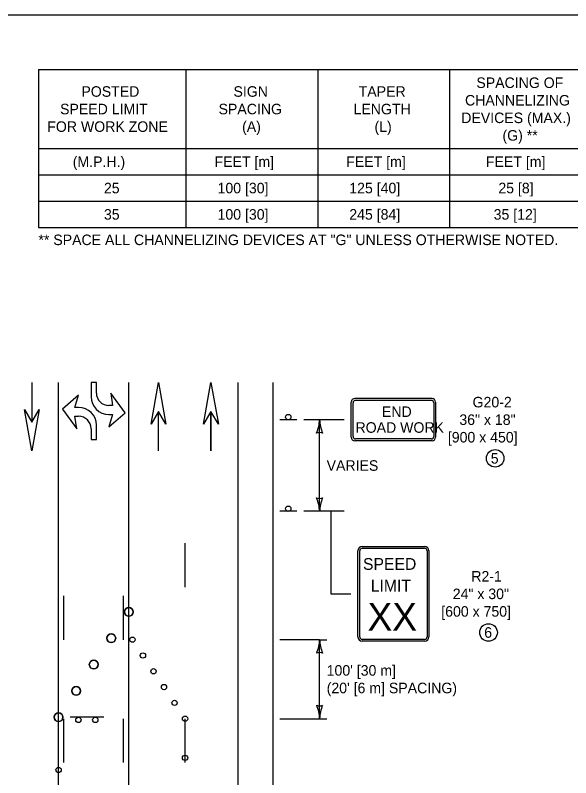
# Model space of a CAD drawing. Extents: x 49991.4 to 50021, y 49987.6 to 50011.4.
# Drawn here: x 50002.533 to 50005.696, y 50006.919 to 50011.263 of the extents above; entities that cross this region are included whole.
import ezdxf

# ---------------------------------------------------------------- set-up
doc = ezdxf.new("R2010")
doc.units = 0
for name, color, linetype in [('Level 1', 7, 'Continuous'), ('Level 2', 7, 'Continuous'), ('Level 3', 7, 'Continuous')]:
    doc.layers.add(name, color=color, linetype=linetype)

msp = doc.modelspace()

# ---------------------------------------------------------------- linework, layer by layer
at = {"layer": 'Level 1'}
for p, q in [((50002.6282, 50009.1708), (50002.6282, 50008.9449)), ((50002.6284, 50009.1708), (50002.6284, 50008.9449)), ((50002.7802, 50000.6526), (50002.7802, 50009.1708)), ((50002.9955, 50009.1708), (50002.9649, 50009.1708)), ((50002.9649, 50009.1708), (50002.9649, 50009.09)), ((50002.9955, 50009.1102), (50002.9955, 50009.1708)), ((50003.1802, 50000.6526), (50003.1802, 50009.1708)), ((50003.8002, 50009.1708), (50003.8002, 50000.6526)), ((50004.0002, 50009.1708), (50004.0002, 50000.6526)), ((50002.8934, 50009.0995), (50002.8015, 50009.0187)), ((50002.873, 50009.0288), (50002.8934, 50009.0995)), ((50003.1588, 50008.999), (50003.0772, 50009.1102)), ((50003.0772, 50009.1102), (50003.0874, 50009.0394)), ((50003.0609, 50009.0445), (50003.0609, 50009.0445)), ((50003.0874, 50009.0394), (50003.067, 50009.0394)), ((50004.4465, 50008.8591), (50004.4465, 50009.0591)), ((50004.4565, 50008.8641), (50004.4565, 50009.0541)), ((50004.9065, 50009.0791), (50004.4665, 50009.0791)), ((50004.9015, 50009.0691), (50004.4715, 50009.0691)), ((50004.9165, 50009.0541), (50004.9165, 50008.8641)), ((50004.9265, 50009.0591), (50004.9265, 50008.8591)), ((50002.8015, 50009.0187), (50002.8832, 50008.9075)), ((50002.8934, 50009.0288), (50002.873, 50009.0288)), ((50003.067, 50008.9181), (50003.1588, 50008.999)), ((50003.3491, 50008.7807), (50003.3491, 50009.0066)), ((50003.3495, 50008.7807), (50003.3495, 50009.0066)), ((50003.6477, 50008.7807), (50003.6477, 50009.0066)), ((50003.6481, 50008.7807), (50003.6481, 50009.0066)), ((50002.8832, 50008.9075), (50002.873, 50008.9783)), ((50002.873, 50008.9783), (50002.8934, 50008.9783)), ((50002.8995, 50008.9732), (50002.8995, 50008.9732)), ((50003.067, 50008.9889), (50003.0874, 50008.9889)), ((50003.0874, 50008.9889), (50003.067, 50008.9181)), ((50004.1362, 50008.9591), (50004.0402, 50008.9591)), ((50002.9649, 50008.9075), (50002.9649, 50008.8468)), ((50002.9955, 50008.8468), (50002.9955, 50008.9277)), ((50002.9649, 50008.8468), (50002.9955, 50008.8468)), ((50004.9064, 50008.8391), (50004.4664, 50008.8391)), ((50004.9015, 50008.8491), (50004.4715, 50008.8491)), ((50004.1362, 50008.437), (50004.0402, 50008.437)), ((50003.5003, 50008.0059), (50003.5003, 50008.2559)), ((50004.4839, 50007.7222), (50004.4839, 50008.2116)), ((50004.4944, 50007.7222), (50004.4944, 50008.2116)), ((50004.5092, 50008.237), (50004.8636, 50008.237)), ((50004.5092, 50008.2264), (50004.8636, 50008.2264)), ((50004.6864, 50008.237), (50004.6864, 50008.237)), ((50004.8784, 50008.2116), (50004.8784, 50007.7222)), ((50004.8889, 50008.2116), (50004.8889, 50007.7222)), ((50002.8102, 50007.7059), (50002.8102, 50007.9559)), ((50003.1502, 50007.7059), (50003.1502, 50007.9559)), ((50004.8636, 50007.7074), (50004.5092, 50007.7074)), ((50004.8636, 50007.6969), (50004.5092, 50007.6969)), ((50002.8102, 50007.0059), (50002.8102, 50007.2559)), ((50002.9412, 50007.2639), (50002.8452, 50007.2639)), ((50003.0372, 50007.2639), (50002.9412, 50007.2639)), ((50003.1502, 50007.0059), (50003.1502, 50007.2559)), ((50003.5003, 50007.0059), (50003.5003, 50007.2559))]:
    msp.add_line(p, q, dxfattribs=at)
for points in [[(50008.6146, 50011.2628), (50000.3356, 50011.2628), (50000.3356, 50000.0624), (50008.6146, 50000.0624)], [(50003.3075, 50008.9343), (50003.3491, 50009.1708), (50003.3911, 50008.9343), (50003.3491, 50009.0065)], [(50003.6061, 50008.9343), (50003.6477, 50009.1708), (50003.6897, 50008.9343), (50003.6477, 50009.0065)], [(50002.6702, 50009.0172), (50002.6284, 50008.7807), (50002.5866, 50009.0172), (50002.6284, 50008.945)]]:
    msp.add_lwpolyline(points, close=True, dxfattribs=at)
for centre, radius in [((50004.0881, 50008.9743), 0.0152), ((50004.0881, 50008.4521), 0.0152), ((50003.1802, 50007.8639), 0.025), ((50003.0802, 50007.7139), 0.025), ((50003.2005, 50007.7059), 0.015), ((50003.2604, 50007.6159), 0.015), ((50002.9802, 50007.5639), 0.025), ((50003.3204, 50007.5259), 0.015), ((50002.8802, 50007.4139), 0.025), ((50003.3804, 50007.4359), 0.015), ((50003.4404, 50007.3459), 0.015), ((50002.7802, 50007.2639), 0.025), ((50002.8932, 50007.2487), 0.0152), ((50002.9892, 50007.2487), 0.0152), ((50003.5003, 50007.2559), 0.015), ((50003.5003, 50007.0329), 0.015), ((50002.7802, 50006.9639), 0.015)]:
    msp.add_circle(centre, radius, dxfattribs=at)
for centre, radius, start, end in [((50004.4665, 50009.0591), 0.02, 90, 180), ((50004.4715, 50009.0541), 0.015, 90, 180), ((50004.9015, 50009.0541), 0.015, 360, 90), ((50004.9065, 50009.0591), 0.02, 360, 90), ((50004.4715, 50008.8641), 0.015, 180, 270), ((50004.9015, 50008.8641), 0.015, 270, 360), ((50004.4664, 50008.8591), 0.02, 180, 270), ((50004.9064, 50008.8591), 0.02, 270, 360), ((50004.5092, 50008.2116), 0.0253, 90, 180), ((50004.5092, 50008.2116), 0.0148, 90, 180), ((50004.8636, 50008.2116), 0.0253, 0, 90), ((50004.8636, 50008.2116), 0.0148, 0, 90), ((50003.1802, 50007.8639), 0.025, 0, 180), ((50003.1802, 50007.8639), 0.025, 180, 0), ((50003.0802, 50007.7139), 0.025, 0, 180), ((50003.0802, 50007.7139), 0.025, 180, 0), ((50004.5092, 50007.7222), 0.0253, 180, 270), ((50004.5092, 50007.7222), 0.0148, 180, 270), ((50004.8636, 50007.7222), 0.0148, 270, 360), ((50004.8636, 50007.7222), 0.0253, 270, 360), ((50002.9802, 50007.5639), 0.025, 0, 180), ((50002.9802, 50007.5639), 0.025, 180, 0), ((50002.8802, 50007.4139), 0.025, 0, 180), ((50002.8802, 50007.4139), 0.025, 180, 0), ((50002.7802, 50007.2639), 0.025, 0, 180), ((50002.7802, 50007.2639), 0.025, 180, 0)]:
    msp.add_arc(centre, radius, start, end, dxfattribs=at)
for centre, major_axis in [((50003.067, 50009.09), (-0.1021, 0)), ((50003.067, 50009.1102), (-0.0715, 0)), ((50002.8934, 50008.9277), (0.1021, 0)), ((50002.8934, 50008.9075), (0.0715, 0))]:
    msp.add_ellipse(centre, major_axis=major_axis, ratio=0.990099, start_param=0, end_param=1.570796, dxfattribs=at)
at = {"layer": 'Level 2'}
for p, q in [((50002.6653, 50010.9535), (50006.5953, 50010.9535)), ((50002.6653, 50010.9535), (50002.6653, 50010.0535)), ((50003.5053, 50010.9535), (50003.5053, 50010.0535)), ((50004.2553, 50010.9535), (50004.2553, 50010.0535)), ((50005.0053, 50010.9535), (50005.0053, 50010.0535)), ((50002.6653, 50010.5035), (50006.5953, 50010.5035)), ((50002.6653, 50010.3535), (50006.5953, 50010.3535)), ((50002.6653, 50010.2035), (50006.5953, 50010.2035)), ((50002.6653, 50010.0535), (50006.5953, 50010.0535))]:
    msp.add_line(p, q, dxfattribs=at)
for centre in [(50005.2657, 50008.739), (50005.2281, 50007.7468)]:
    msp.add_circle(centre, 0.0501, dxfattribs=at)
at = {"layer": 'Level 3'}
for p, q in [((50004.4065, 50008.9591), (50004.1762, 50008.9591)), ((50004.2662, 50008.437), (50004.2662, 50008.9591)), ((50004.4065, 50008.437), (50004.1762, 50008.437)), ((50004.2665, 50007.7059), (50004.0402, 50007.7059)), ((50004.2665, 50007.2559), (50004.2665, 50007.7059)), ((50004.2665, 50007.7059), (50004.3065, 50007.7059)), ((50004.2665, 50007.2559), (50004.2665, 50007.5714)), ((50004.0402, 50007.2559), (50004.3065, 50007.2559))]:
    msp.add_line(p, q, dxfattribs=at)
msp.add_lwpolyline([(50004.3306, 50008.437), (50004.3306, 50007.9669), (50004.4439, 50007.9669)], dxfattribs=at)
for centre, radius, start, end in [((50004.0441, 50008.9683), 0.2223, 337.456, 357.6395), ((50004.4989, 50008.9706), 0.233, 182.8273, 202.0772), ((50004.2662, 50008.8309), 0.0548, 72.1388, 107.8612), ((50004.2662, 50008.5652), 0.0548, 252.1388, 287.8612), ((50004.0335, 50008.4255), 0.233, 2.8273, 22.0772), ((50004.4883, 50008.4278), 0.2223, 157.456, 177.6395), ((50004.0444, 50007.7151), 0.2223, 337.456, 357.6395), ((50004.4992, 50007.7174), 0.233, 182.8273, 202.0772), ((50004.2665, 50007.5777), 0.0548, 72.1388, 107.8612), ((50004.2665, 50007.3841), 0.0548, 252.1388, 287.8612), ((50004.0338, 50007.2444), 0.233, 2.8273, 22.0772), ((50004.4886, 50007.2467), 0.2223, 157.456, 177.6395)]:
    msp.add_arc(centre, radius, start, end, dxfattribs=at)

# ---------------------------------------------------------------- texts
at = {"layer": 'Level 1'}
for s, p in [('END', (50004.6213, 50008.9745)), ('ROAD WORK', (50004.4706, 50008.8845))]:
    msp.add_text(s, height=0.06, rotation=360, dxfattribs=at).set_placement(p)
for s, height, p in [('SPEED', 0.06695, (50004.5133, 50008.1037)), ('LIMIT', 0.06695, (50004.5576, 50007.9799)), ('XX', 0.15772, (50004.5393, 50007.758))]:
    msp.add_text(s, height=height, dxfattribs=at).set_placement(p)
at = {"layer": 'Level 2'}
for s, p in [('SPACING OF', (50005.1588, 50010.8485)), ('POSTED', (50002.91, 50010.7985)), ('SIGN', (50003.7759, 50010.7985)), ('TAPER', (50004.4886, 50010.7985)), ('CHANNELIZING', (50005.0941, 50010.7485)), ('SPEED LIMIT', (50002.7887, 50010.6985)), ('SPACING', (50003.6909, 50010.6985)), ('LENGTH', (50004.4594, 50010.6985)), ('DEVICES (MAX.)', (50005.0726, 50010.6485)), ('FOR WORK ZONE', (50002.7157, 50010.5985)), ('(A)', (50003.8249, 50010.5985)), ('(L)', (50004.5787, 50010.5985)), ('(G) **', (50005.3074, 50010.5485)), ('(M.P.H.)', (50002.8608, 50010.3985)), ('FEET [m]', (50003.668, 50010.3985)), ('FEET [m]', (50004.418, 50010.3985)), ('FEET [m]', (50005.213, 50010.3985)), ('25', (50003.0383, 50010.2485)), ('100 [30]', (50003.6852, 50010.2485)), ('125 [40]', (50004.4352, 50010.2485)), ('25 [8]', (50005.284, 50010.2485)), ('35', (50003.0384, 50010.0985)), ('100 [30]', (50003.6852, 50010.0985)), ('245 [84]', (50004.4352, 50010.0985)), ('35 [12]', (50005.2571, 50010.0985)), ('** SPACE ALL CHANNELIZING DEVICES AT "G" UNLESS OTHERWISE NOTED.', (50002.6653, 50009.9535)), ('G20-2', (50005.1371, 50009.0291)), ('36" x 18"', (50005.0619, 50008.9291)), ('[900 x 450]', (50004.9964, 50008.8291)), ('5', (50005.2407, 50008.709)), ('R2-1', (50005.1299, 50008.0369)), ('24" x 30"', (50005.0244, 50007.9369)), ('[600 x 750]', (50004.9588, 50007.8369)), ('6', (50005.2036, 50007.7168)), ("100' [30 m]", (50004.3065, 50007.5009)), ("(20' [6 m] SPACING)", (50004.3065, 50007.4009))]:
    msp.add_text(s, height=0.06, dxfattribs=at).set_placement(p)
msp.add_text('VARIES', height=0.06, rotation=360, dxfattribs=at).set_placement((50004.3062, 50008.668))

doc.saveas('drawing.dxf')
